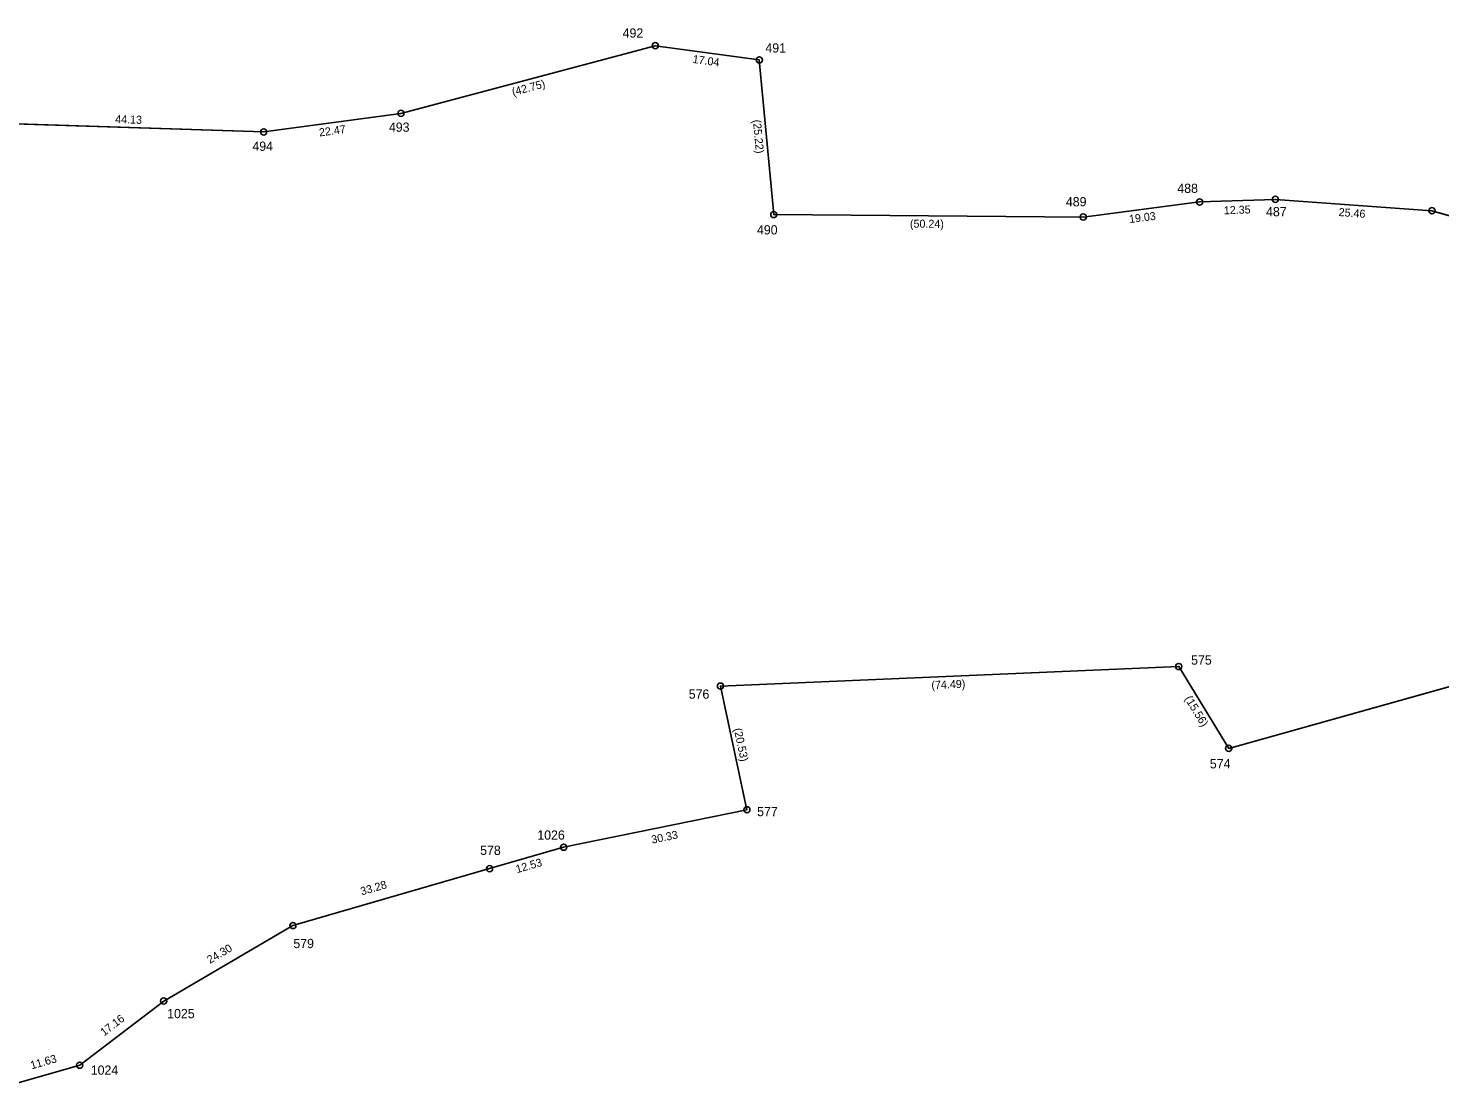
# Model space of a CAD drawing. Extents: x -555170 to -550532, y -1039598 to -1034701.
# Drawn here: x -554491.3 to -554262.1, y -1037853.3 to -1037681.7 of the extents above; entities that cross this region are included whole.
import ezdxf

# ---------------------------------------------------------------- set-up
doc = ezdxf.new("R2010")
doc.units = 0
for name, color, linetype in [('Vrstva 10', 7, 'Continuous'), ('Vrstva 40', 7, 'Continuous'), ('Vrstva 43', 7, 'Continuous'), ('Vrstva 48', 7, 'Continuous')]:
    doc.layers.add(name, color=color, linetype=linetype)

msp = doc.modelspace()

# ---------------------------------------------------------------- linework, layer by layer
at = {"layer": 'Vrstva 40'}
for p, q in [((-554389.47, -1037684.57), (-554430.79, -1037695.56)), ((-554372.58, -1037686.88), (-554389.47, -1037684.57)), ((-554370.22, -1037711.99), (-554372.58, -1037686.88)), ((-554430.79, -1037695.56), (-554453.05, -1037698.58)), ((-554453.05, -1037698.58), (-554497.11, -1037697.13)), ((-554301.07, -1037709.95), (-554319.98, -1037712.39)), ((-554288.75, -1037709.52), (-554301.07, -1037709.95)), ((-554263.34, -1037711.37), (-554288.75, -1037709.52)), ((-554319.98, -1037712.39), (-554370.22, -1037711.99)), ((-554229.79, -1037720.89), (-554263.34, -1037711.37)), ((-554296.34, -1037798.66), (-554203.1, -1037772.53)), ((-554378.88, -1037788.55), (-554304.45, -1037785.37)), ((-554304.45, -1037785.37), (-554296.34, -1037798.66)), ((-554374.59, -1037808.63), (-554378.88, -1037788.55)), ((-554404.35, -1037814.71), (-554374.59, -1037808.63)), ((-554416.39, -1037818.19), (-554404.35, -1037814.71)), ((-554448.32, -1037827.43), (-554416.39, -1037818.19)), ((-554469.3, -1037839.68), (-554448.32, -1037827.43)), ((-554482.94, -1037850.1), (-554469.3, -1037839.68)), ((-554494.07, -1037853.28), (-554482.94, -1037850.1))]:
    msp.add_line(p, q, dxfattribs=at)
at = {"layer": 'Vrstva 43'}
for p, q in [((-554389.47, -1037684.57), (-554389.47, -1037684.57)), ((-554372.58, -1037686.88), (-554372.58, -1037686.88)), ((-554430.79, -1037695.56), (-554430.79, -1037695.56)), ((-554453.05, -1037698.58), (-554453.05, -1037698.58)), ((-554301.07, -1037709.95), (-554301.07, -1037709.95)), ((-554288.75, -1037709.52), (-554288.75, -1037709.52)), ((-554370.22, -1037711.99), (-554370.22, -1037711.99)), ((-554319.98, -1037712.39), (-554319.98, -1037712.39)), ((-554263.34, -1037711.37), (-554263.34, -1037711.37)), ((-554304.45, -1037785.37), (-554304.45, -1037785.37)), ((-554378.88, -1037788.55), (-554378.88, -1037788.55)), ((-554296.34, -1037798.66), (-554296.34, -1037798.66)), ((-554374.59, -1037808.63), (-554374.59, -1037808.63)), ((-554404.35, -1037814.71), (-554404.35, -1037814.71)), ((-554416.39, -1037818.19), (-554416.39, -1037818.19)), ((-554448.32, -1037827.43), (-554448.32, -1037827.43)), ((-554469.3, -1037839.68), (-554469.3, -1037839.68)), ((-554482.94, -1037850.1), (-554482.94, -1037850.1))]:
    msp.add_line(p, q, dxfattribs=at)
for centre, radius in [((-554389.48, -1037684.57), 0.5), ((-554389.48, -1037684.57), 0.01), ((-554372.58, -1037686.88), 0.5), ((-554372.58, -1037686.88), 0.01), ((-554430.79, -1037695.56), 0.5), ((-554430.79, -1037695.56), 0.01), ((-554453.05, -1037698.58), 0.5), ((-554453.05, -1037698.58), 0.01), ((-554301.07, -1037709.95), 0.5), ((-554301.07, -1037709.95), 0.01), ((-554288.75, -1037709.52), 0.5), ((-554288.75, -1037709.52), 0.01), ((-554370.22, -1037711.99), 0.5), ((-554370.22, -1037711.99), 0.01), ((-554319.98, -1037712.39), 0.5), ((-554319.98, -1037712.39), 0.01), ((-554263.34, -1037711.37), 0.5), ((-554263.34, -1037711.37), 0.01), ((-554304.45, -1037785.37), 0.5), ((-554304.45, -1037785.37), 0.01), ((-554378.88, -1037788.55), 0.5), ((-554378.88, -1037788.55), 0.01), ((-554296.34, -1037798.66), 0.5), ((-554296.34, -1037798.66), 0.01), ((-554374.59, -1037808.63), 0.5), ((-554374.59, -1037808.63), 0.01), ((-554404.35, -1037814.71), 0.5), ((-554404.35, -1037814.71), 0.01), ((-554416.39, -1037818.19), 0.5), ((-554416.39, -1037818.19), 0.01), ((-554448.32, -1037827.43), 0.5), ((-554448.32, -1037827.43), 0.01), ((-554469.3, -1037839.68), 0.5), ((-554469.3, -1037839.68), 0.01), ((-554482.94, -1037850.1), 0.5), ((-554482.94, -1037850.1), 0.01)]:
    msp.add_circle(centre, radius, dxfattribs=at)
at = {"layer": 'Vrstva 48'}
for points in [[(-554497.11, -1037697.13), (-554453.05, -1037698.58), (-554430.79, -1037695.56), (-554389.47, -1037684.57), (-554372.58, -1037686.88), (-554370.22, -1037711.99), (-554319.98, -1037712.39), (-554301.07, -1037709.95), (-554288.75, -1037709.52), (-554263.34, -1037711.37), (-554229.79, -1037720.89)], [(-554203.1, -1037772.53), (-554296.34, -1037798.66), (-554304.45, -1037785.37), (-554378.88, -1037788.55), (-554374.59, -1037808.63), (-554404.35, -1037814.71), (-554416.39, -1037818.19), (-554448.32, -1037827.43), (-554469.3, -1037839.68), (-554482.94, -1037850.1), (-554494.07, -1037853.28)]]:
    msp.add_lwpolyline(points, dxfattribs=at)

# ---------------------------------------------------------------- texts
at = {"layer": 'Vrstva 10'}
for s, rotation, p in [('17.04', 352.221, (-554383.46, -1037687.36)), ('(42.75)', 14.8947, (-554412.56, -1037692.73)), ('44.13', 358.1135, (-554477.2, -1037697.13)), ('22.47', 7.726, (-554443.99, -1037699.32)), ('(25.22)', 275.3638, (-554373.62, -1037696.64)), ('19.03', 7.3505, (-554312.44, -1037713.38)), ('12.35', 1.998, (-554297.12, -1037711.96)), ('25.46', 355.8309, (-554278.53, -1037712.22)), ('(50.24)', 359.5422, (-554348.12, -1037714.11)), ('(74.49)', 2.443, (-554344.6, -1037789.04)), ('(15.56)', 301.4037, (-554303.55, -1037790.59)), ('(20.53)', 282.0597, (-554376.73, -1037795.5)), ('30.33', 11.5467, (-554389.97, -1037814.14)), ('12.53', 16.1276, (-554411.92, -1037818.93)), ('33.28', 16.1367, (-554437.14, -1037822.54)), ('24.30', 30.2834, (-554461.8, -1037833.66)), ('17.16', 37.3773, (-554478.99, -1037845.43)), ('11.63', 15.9454, (-554490.75, -1037850.78))]:
    msp.add_text(s, height=1.3, rotation=rotation, dxfattribs=at).set_placement(p)
at = {"layer": 'Vrstva 43'}
for s, p in [('492', (-554394.77, -1037683.26)), ('491', (-554371.59, -1037685.69)), ('493', (-554432.73, -1037698.55)), ('494', (-554454.9, -1037701.64)), ('488', (-554304.69, -1037708.48)), ('489', (-554322.79, -1037710.66)), ('487', (-554290.28, -1037712.27)), ('490', (-554372.96, -1037715.22)), ('575', (-554302.45, -1037785.07)), ('576', (-554384.04, -1037790.6)), ('574', (-554299.41, -1037801.91)), ('577', (-554372.93, -1037809.67)), ('1026', (-554408.63, -1037813.48)), ('578', (-554417.91, -1037815.96)), ('579', (-554448.25, -1037831.09)), ('1025', (-554468.74, -1037842.47)), ('1024', (-554481.15, -1037851.65))]:
    msp.add_text(s, height=1.5, dxfattribs=at).set_placement(p)

doc.saveas('drawing.dxf')
